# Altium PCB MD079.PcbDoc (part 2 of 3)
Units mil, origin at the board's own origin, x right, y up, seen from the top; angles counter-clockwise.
Board outline 4255 x 2850 mil, 4 copper layers (Top Layer, Ground, Power, Bottom Layer), stack 61.6 mil thick; 171 components, 88 nets, 422 pads, 405 vias.
Unrouted connection lines stored in the file: 3.
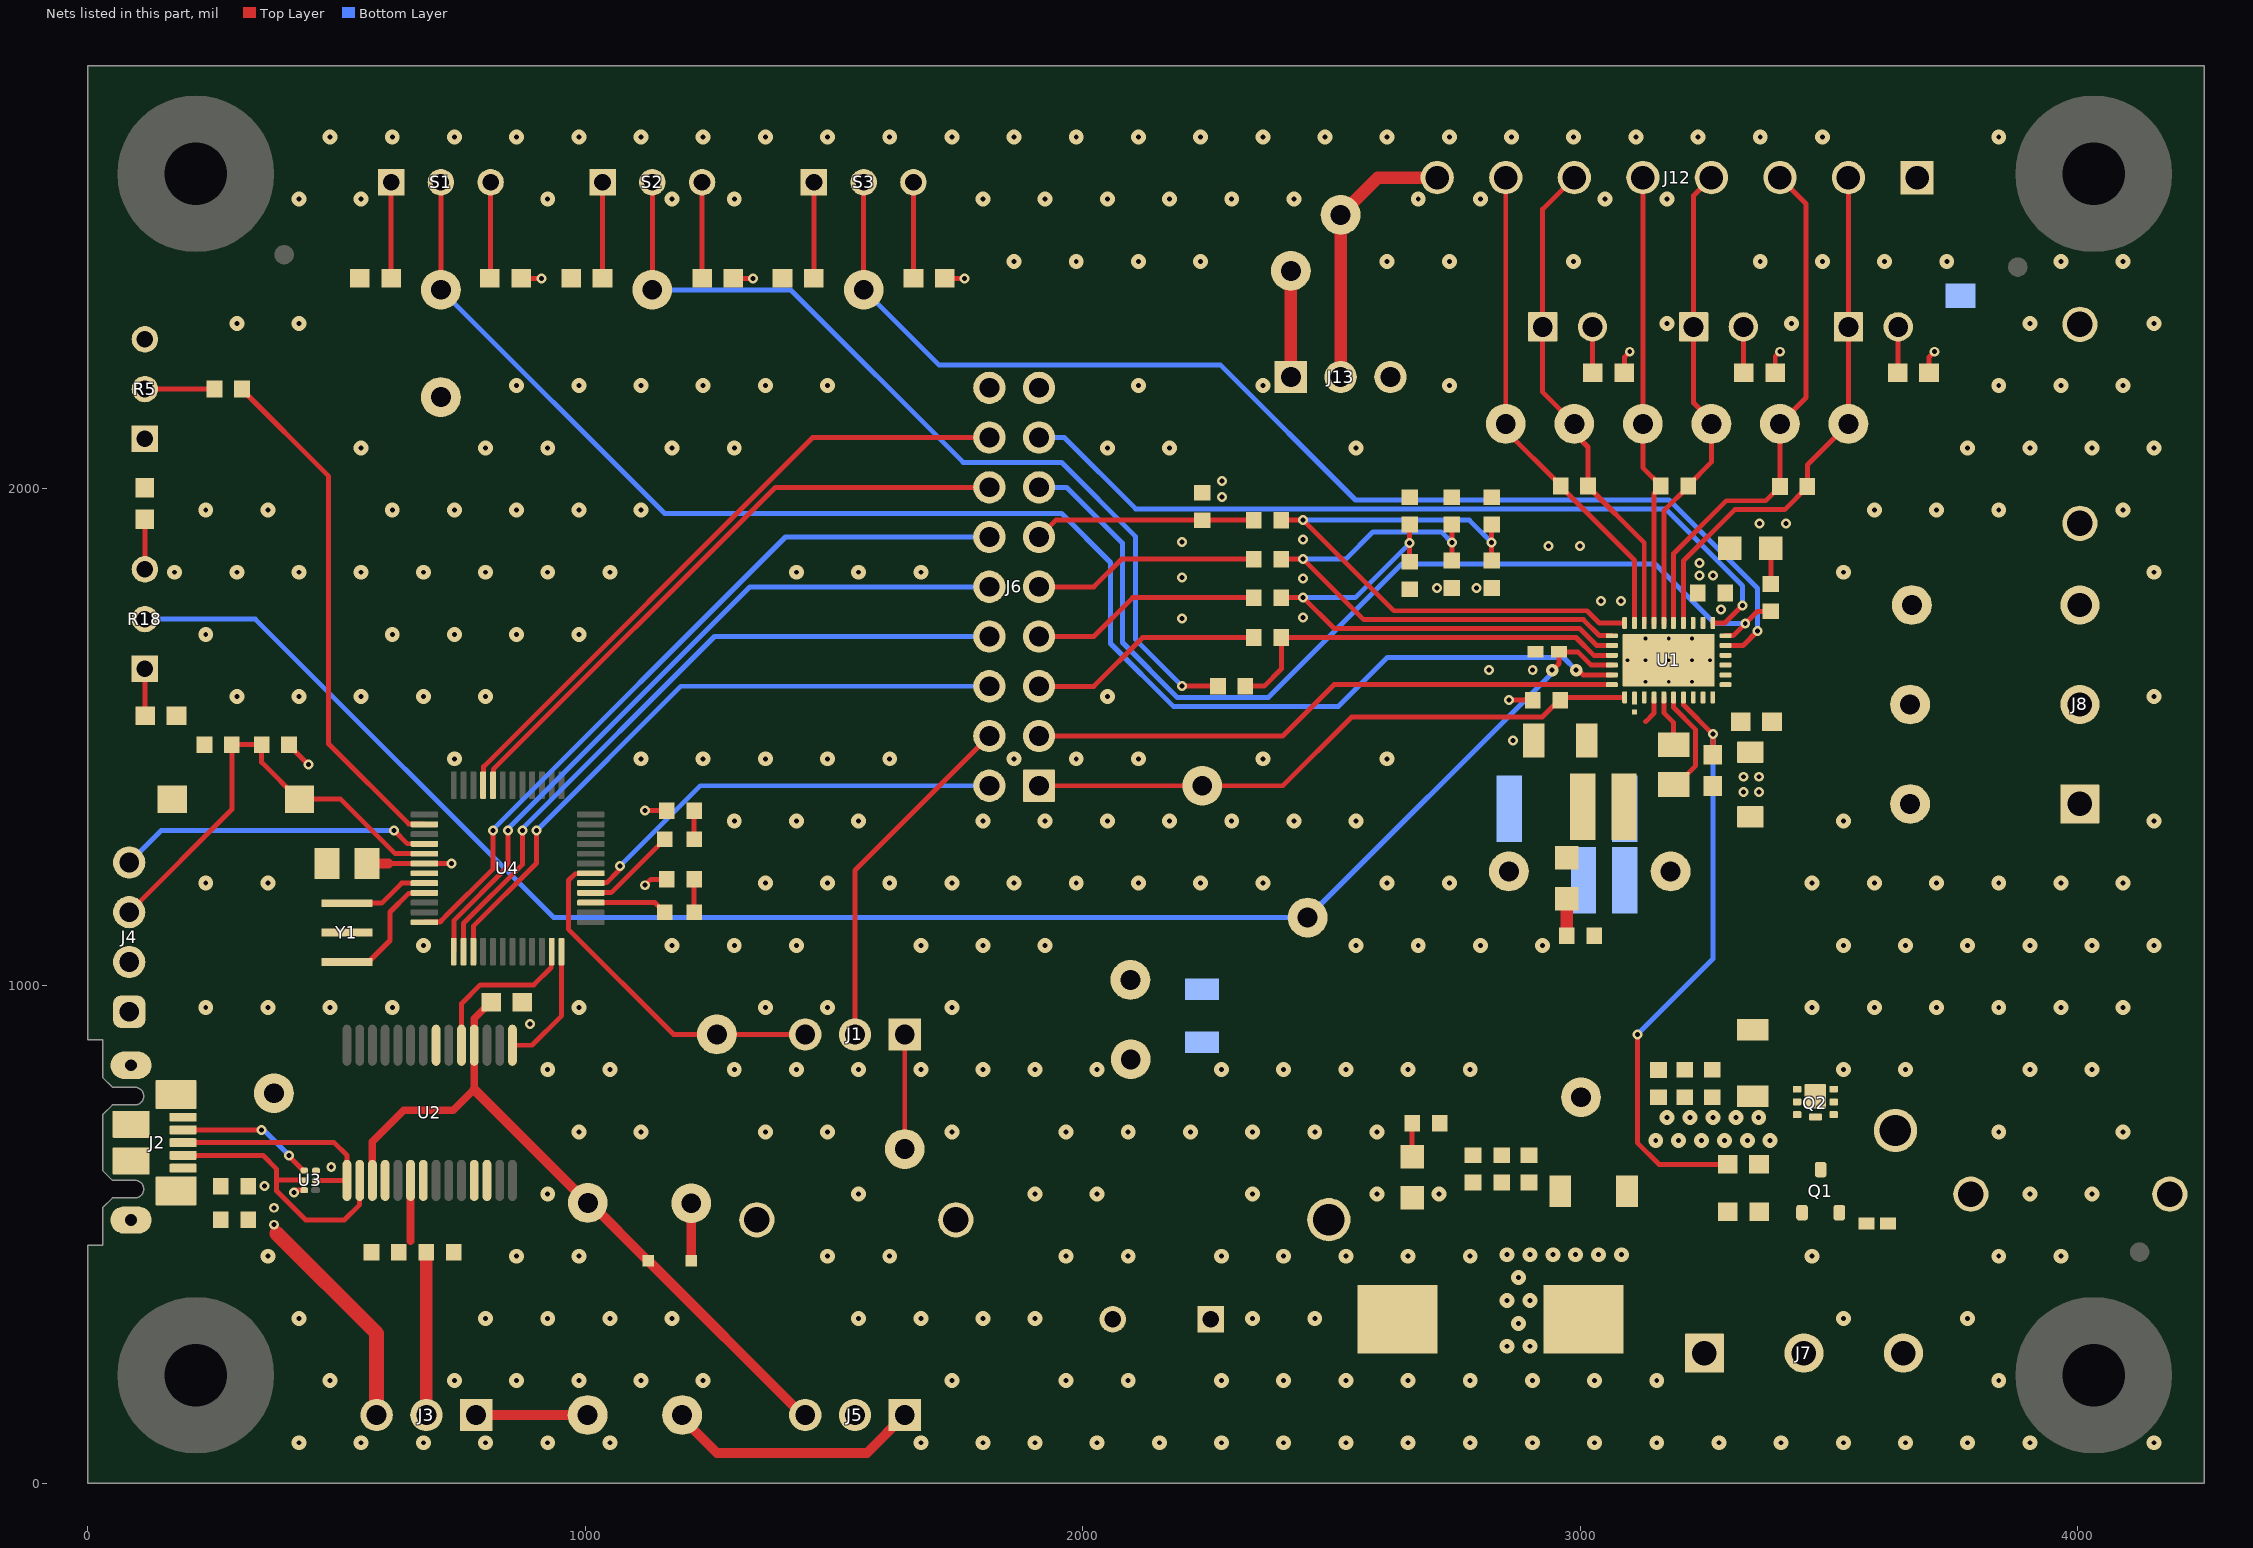
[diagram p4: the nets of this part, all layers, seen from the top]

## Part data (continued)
C17 C20: library part CMP-0007082-4, "CAP, CERM, 0.01 uF, 100 V, +/- 10%, X7R, AEC-Q200 Grade 1, 0603", Cap_Case=0603, Manufacturer=TDK, Supplier Part Number 1=445-5812-1-ND, TempCo=X7R, Tolerance_%=10%, Value1="0.235428 ohm", Value2=100V, ValueDisplayed=0.01uF
C18 C19: library part CMP-0006723-4, "CAP, CERM, 1000 pF, 100 V, +/- 5%, X7R, 0603", Cap_Case=0603, Manufacturer=AVX, Supplier Part Number 1=478-3698-1-ND, TempCo=X7R, Tolerance_%=5%, Value1="0.276 ohm", Value2=100V, ValueDisplayed=1000pF
C23 C24 C25: library part CMP-0083626-1, "CAP, CERM, 0.1 µF, 16 V,+/- 10%, X7R, AEC-Q200 Grade 1, 0603", Cap_Case=0603, Manufacturer=AVX, Supplier Part Number 1=478-9382-1-ND, TempCo=X7R, Tolerance_%=10%, Value2=16V, ValueDisplayed=0.1µF
D1 D3: library part CMP-0002888-2, "LED, Green, SMD", Color=Green, Manufacturer=Lite-On, Value1=W, Value2=2V
D2: library part CMP-0002829-3, "LED, Red, SMD", Color=red, Manufacturer=Lite-On, Value1=W, Value2=2V
D4: library part CMP-0028882-2, "Diode, Schottky, 40 V, 0.75 A, AEC-Q101, SOD-323", Manufacturer="Infineon Technologies", Value1=0.75A, Value2=0.74V
D5: library part CMP-0078131-2, "LED, Red, SMD", Color=Red, Manufacturer=Lite-On, Power_TotalModule=62.5mW, Value1=.0625W, Value2=2V
D6: library part CMP-0002827-3, "LED, Green, SMD", Color=green, Manufacturer=Lite-On, Power_TotalModule=100mW, Value1=0.1W, Value2=2.1V
D7: library part CMP-0076979-3, "Diode, Switching, 100 V, 0.25 A, SOD-523", Manufacturer=Nexperia, Value1=0.25A, Value2=1.25V
FID1 FID2 FID3: library part CMP-0077181-1, "Fiducial mark.  There is nothing to buy or mount.", Manufacturer=N/A
H1 H2 H3 H4: library part CMP-0003617-1, "Machine Screw, Round, #4-40 x 1/4, Nylon, Philips panhead", Manufacturer="B&F Fastener Supply", Supplier Part Number 1=H542-ND
H5 H6 H7 H8: library part CMP-0003610-1, "Standoff, Hex, 0.5\"L #4-40 Nylon", Manufacturer=Keystone, PartNumber=1902C, Supplier Part Number 1=36-1902C-ND
J1 J3 J5 J13: library part CMP-0002334-1, "Header, 100mil, 3x1, Gold, TH", Manufacturer="Sullins Connector Solutions", PartNumber=PBC03SAAN, Supplier Part Number 1=S1011E-03-ND
J2: library part CMP-0055311-1, "Receptacle, USB 2.0, Micro B, 5 Position, R/A, SMT", Color=Black, Current_A=1.8A, Manufacturer=Molex, Supplier Part Number 1=WM11263CT-ND, Voltage_V=30V
J4: library part CMP-0075409-2, "Header, 100mil, 4x1, Gold, TH", Color=Black, Current_A=6.3A, Manufacturer=Samtec, Supplier Part Number 1=SAM1029-04-ND, Voltage_V=550V
J6: library part CMP-0075464-1, "Header, 100mil, 9x2, Gold, TH", Color=Black, Current_A=6.3A, Manufacturer=Samtec, Supplier Part Number 1=SAM1028-09-ND, Voltage_V=550V
J7 J8: library part CMP-0074911-1, "Terminal Block, 5.08 mm, 3x1, Brass, TH", Color=Blue, Current_A=15A, Manufacturer="On-Shore Technology", PartNumber=ED120/3DS, Supplier Part Number 1=ED1610-ND, Voltage_V=300V
J9 J10 J11: library part CMP-0002337-1, "Header, 100mil, 2x1, Tin, TH", Color=Black, Current_A=3A, Manufacturer="Sullins Connector Solutions", Supplier Part Number 1=S1012E-02-ND, Voltage_V=1.8kV
J12: library part CMP-0074957-2, "Terminal Block, 8x1, 3.5mm, TH", Manufacturer="On-Shore Technology", Supplier Part Number 1=ED2641-ND
L1: library part CMP-0064683-2, "Inductor, Shielded, Powdered Iron, 47 uH, 0.39 A, 2.3 ohm, AEC-Q200 Grade 1, SMD", Manufacturer="Wurth Elektronik", Supplier Part Number 1=732-6947-1-ND, Value1="2.3 ohm", Value2=0.39A, ValueDisplayed=47uH
L2: library part CMP-0064681-2, "Inductor, Shielded, Powdered Iron, 22 uH, 0.6 A, 1.04 ohm, AEC-Q200 Grade 1, SMD", Manufacturer="Wurth Elektronik", Supplier Part Number 1=732-6945-1-ND, Value1="1.04 ohm", Value2=0.6A, ValueDisplayed=22uH
L3: library part CMP-0084877-1, "Inductor, Ferrite Bead, Ferrite, 3 A, 120 ohm, AEC-Q200 Grade 1, SMD", Manufacturer=MuRata, Value1="120 ohm", Value2=3A
L4: library part CMP-0056795-1, "Inductor, Shielded, Powdered Iron, 1 uH, 18 A, 0.003 ohm, AEC-Q200 Grade 1, SMD", Manufacturer=Bourns, Supplier Part Number 1=SRP1038A-1R0MCT-ND, Value1="0.003 ohm", Value2=18A, ValueDisplayed=1uH
LBL1: library part CMP-0003625-1, Manufacturer=Brady, Supplier Part Number 1=97C5133
Logo1: library part CMP-0074844-1
Logo2: library part CMP-0074838-1, "Texas Instrument Corporate Signature"
Logo3: library part CMP-0074847-1, "FCC_disclaimer"
Logo4: library part CMP-0074769-3, Manufacturer="Texas Instruments"
LOGO5 LOGO6: library part CMP-0074837-2, "IEC 61010-1 Hot Surface Warning", Manufacturer="Texas Instruments"
NT1 NT2: library part CMP-0078142-6, "Single point connection between nets.", Manufacturer=N/A
Q1: library part CMP-0000467-2, "Transistor, NPN, 80 V, 1.5 A, AEC-Q101, SOT-23", Manufacturer="Diodes Inc.", Supplier Part Number 1=FMMT620CT-ND, Value1="1.5 A", Value2=900
Q2: library part CMP-0088880-1, "N-Channel 40V 8A (Ta) 15W (Tc) Surface Mount DFN2020MD-6", Digikey Part Number=1727-7413-1-ND, Drain To Source Breakdown Voltage=40V, Input Capacitace At Vds="637pF @ 20V", Manufacturer=Nexperia, Mouser Part Number=771-BUK9D23-40EX, Operating Temperature Range="-55°C to +175°C", Power_W=2.3W, Pulse Drain Current=76A, Typ Forward Diode Voltage=0.8V
R1 R2 R3 R6 R7 R8 R32 R33 R34 R35 R36: library part CMP-0022746-5, "RES, 10.0 k, 1%, 0.1 W, 0603", Manufacturer=Yageo, Power_W=100mW, Supplier Part Number 1=311-10.0KHRCT-ND, TempCo="100 ppm/C", Tolerance_%=1%, Value2=0.1W, Value_Code=10k0, ValueDisplayed=10.0k
R4 R13 R14 R15 R16 R17 R21 R26 R27: library part CMP-0025874-4, "RES, 0, 5%, 0.1 W, AEC-Q200 Grade 0, 0603", Manufacturer=Panasonic, Power_W=100mW, Supplier Part Number 1=P0.0GCT-ND, TempCo="600 ppm/C", Tolerance_%=5%, Value2=0.1W, Value_Code=0000, ValueDisplayed=0
R5: library part CMP-0001776-2, "Trimmer Potentiometer, 25kohm, 0.5W, TH", Manufacturer=Bourns, Supplier Part Number 1=3352T-253LF-ND
R9 R12: library part CMP-0025830-4, "RES, 5.1 k, 5%, 0.1 W, AEC-Q200 Grade 0, 0603", Manufacturer=Vishay-Dale, Power_W=100mW, Supplier Part Number 1=541-5.1KGCT-ND, TempCo="200 ppm/C", Tolerance_%=5%, Value2=0.1W, Value_Code=5k10, ValueDisplayed=5.1k
R10: library part CMP-0015919-3, "RES, 22, 5%, 1.5 W, AEC-Q200 Grade 0, 2512", Manufacturer=Vishay-Dale, Power_W=1.5W, TempCo="200 ppm/C", Tolerance_%=5%, Value_Code=22R0, ValueDisplayed=22
R11: library part CMP-0023166-5, "RES, 51.1 k, 1%, 0.1 W, 0603", Manufacturer=Yageo, Power_W=100mW, Supplier Part Number 1=311-51.1KHRCT-ND, TempCo="100 ppm/C", Tolerance_%=1%, Value2=0.1W, Value_Code=51k1, ValueDisplayed=51.1k
R18: library part CMP-0093882-3, "10 kOhms 0.5W, 1/2W Through Hole Thumbwheel Potentiometer Top Adjustment", Digikey Part Number=3352T-103LF-ND, Manufacturer=Bourns, Mouser Part Number=652-3352T-1-103LF, Operating Temperature Range="-55°C to +125°C", Power=500mW, Power_W=0.5W, TempCo=100ppm/°C, Tolerance_%=20%, Voltage=250V
R19: library part CMP-0023102-5, "RES, 41.2 k, 1%, 0.1 W, 0603", Manufacturer=Yageo, Power_W=100mW, Supplier Part Number 1=311-41.2KHRCT-ND, TempCo="100 ppm/C", Tolerance_%=1%, Value2=0.1W, Value_Code=41k2, ValueDisplayed=41.2k
R20 R28: library part CMP-0023363-3, "RES, 100 k, 0.1%, 0.1 W, AEC-Q200 Grade 0, 0603", Manufacturer=Panasonic, Power_W=100mW, Supplier Part Number 1=P100KDBCT-ND, TempCo="25 ppm/C", Tolerance_%=0.1%, Value2=0.1W, Value_Code=100k
R22: library part CMP-0022692-3, "RES, 22.0 k, 1%, 0.1 W, AEC-Q200 Grade 0, 0603", Manufacturer=Panasonic, Power_W=100mW, Supplier Part Number 1=P22.0KHCT-ND, TempCo="100 ppm/C", Tolerance_%=1%, Value2=0.1W, Value_Code=22k0, ValueDisplayed=22.0k
R23: library part CMP-0023033-5, "RES, 330, 1%, 0.1 W, 0603", Manufacturer=Yageo, Power_W=100mW, Supplier Part Number 1=311-330HRCT-ND, TempCo="100 ppm/C", Tolerance_%=1%, Value2=0.1W, Value_Code=330R, ValueDisplayed=330
R24: library part CMP-0025899-5, "RES, 1.0 k, 5%, 0.1 W, 0603", Manufacturer=Yageo, Power_W=100mW, Supplier Part Number 1=311-1.0KGRCT-ND, TempCo="100 ppm/C", Tolerance_%=5%, Value2=0.1W, Value_Code=1k00, ValueDisplayed=1.0k
R25: library part CMP-0024300-2, "RES, 4.70 k, 0.1%, 0.1 W, 0603", Manufacturer="Yageo America", Power_W=100mW, TempCo="25 ppm/C", Tolerance_%=0.1%, Value2=0.1W, Value_Code=4k70, ValueDisplayed=4.70k
R29: library part CMP-0025925-5, "RES, 47 k, 5%, 0.1 W, 0603", Manufacturer=Yageo, Power_W=100mW, Supplier Part Number 1=311-47KGRCT-ND, TempCo="100 ppm/C", Tolerance_%=5%, Value2=0.1W, Value_Code=47k0, ValueDisplayed=47k
R30 R31: library part CMP-0025924-5, "RES, 470, 5%, 0.1 W, 0603", Manufacturer=Yageo, Power_W=100mW, Supplier Part Number 1=311-470GRCT-ND, TempCo="100 ppm/C", Tolerance_%=5%, Value2=0.1W, Value_Code=470R, ValueDisplayed=470
R37: library part CMP-0018760-2, "RES, 0, 5%, 0.25 W, AEC-Q200 Grade 0, 1206", Manufacturer=Vishay-Dale, Power_W=250mW, Supplier Part Number 1=541-2239-1-ND, TempCo=ppm/C, Tolerance_%=5%, Value2=0.25W, Value_Code=0000, ValueDisplayed=0
S1 S2 S3: library part CMP-0002155-2, "SWITCH TOGGLE SPDT 0.4VA 28V", CurrentRating_mA=100A, Manufacturer="NKK Switches", PartNumber=B12AP, Supplier Part Number 1=360-1012-ND
S4: library part CMP-0002196-2, "Switch, Tactile, SPST, 12 V, SMD", CurrentRating_mA=50A, Manufacturer="Wurth Elektronik", PartNumber=434121025816, Supplier Part Number 1=31T8978
SH-J1 SH-J2 SH-J3 SH-J4 SH-J5 SH-J6 SH-J7 SH-J8 SH-J9 SH-J10 SH-J11 SH-J12 SH-J13 SH-J14 SH-J15 SH-J16: library part CMP-0003623-3, "Shunt, 100mil, Gold plated, Black", Alternate Manufacturer=3M, Alternate PartNumber=969102-0000-DA, Manufacturer=Samtec, Supplier Part Number 1=SAM8858-ND
TP1 TP2 TP3 TP4 TP5 TP11 TP12 TP21 TP22 TP28 TP29 TP30 TP31: library part CMP-0055139-2, "Test Point, Miniature, White, TH", Color=White, Manufacturer="Keystone Electronics", PartNumber=5002, Supplier Part Number 1=36-5002-ND
TP6 TP7 TP8 TP9 TP10 TP13 TP14 TP23 TP27 TP32 TP33 TP34: library part CMP-0055137-2, "Test Point, Miniature, Red, TH", Color=Red, Manufacturer="Keystone Electronics", PartNumber=5000, Supplier Part Number 1=36-5000-ND
TP15 TP16: library part CMP-0055142-2, "Test Point, Compact, Red, TH", Color=Red, Manufacturer="Keystone Electronics", PartNumber=5005, Supplier Part Number 1=36-5005-ND
TP17 TP24 TP25 TP26: library part CMP-0055138-2, "Test Point, Miniature, Black, TH", Color=Black, Manufacturer="Keystone Electronics", PartNumber=5001, Supplier Part Number 1=36-5001-ND
TP18 TP19 TP20: library part CMP-0075110-1, "1mm Uninsulated Shorting Plug, 10.16mm spacing, TH", Manufacturer=Harwin, PartNumber=D3082-05, Supplier Part Number 1=952-1873-ND
U1: library part CMP-0098493-1, Manufacturer="Texas Instruments", Operating Temperature Range=to
U2: library part CMP-0004774-1, "USB to Serial UART, SSOP28", Manufacturer=FTDI, Supplier Part Number 1=768-1007-1-ND
U3: library part CMP-0043115-3, "4-Channel ESD Protection Array for High-Speed Data Interfaces, DRY0006A (USON-6)", Breakdown Voltage(Min)(V)=6, IO Capacitance(Typ)(pF)=1.6, IO Leakage Current(nA)=1, Manufacturer="Texas Instruments", Operating Temperature Range="-40 to 85 C", Rating=Catalog
U4: library part CMP-0089204-1, "CPU16 MSP430™ FRAM Microcontroller IC 16-Bit 24MHz 32KB (32K x 8) FRAM 48-LQFP (7x7)", Digikey Part Number=296-50261-1-ND, Frequency_Fixed=24MHz, Manufacturer="Texas Instruments", Max Supply Voltage=3.6V, Min Supply Voltage=1.8V, Mouser Part Number=595-MSP430FR2355TPTR, Operating Temperature Range="-40°C to +105°C"
Y1: library part CMP-0084387-1, "Resonator, 4 MHz, 39 pF, AEC-Q200 Grade 1, SMD", Frequency_Fixed=4MHz, Load Capacitance="39 pF", Manufacturer=MuRata
ZZ1: library part CMP-0003616-3
ZZ2: library part CMP-0077236-1
ZZ3: library part CMP-0077237-1
ZZ4: library part CMP-0077238-1

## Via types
v1: diameter 30, hole 10, Top Layer to Bottom Layer, tented both sides, 328 vias
v2: diameter 20, hole 10, Top Layer to Bottom Layer, tented both sides, 32 vias
v3: diameter 20, hole 10, Top Layer to Bottom Layer, 32 vias
v4: diameter 19.68, hole 7.87, Top Layer to Bottom Layer, tented both sides, 11 vias
v5: diameter 25, hole 10, Top Layer to Bottom Layer, 2 vias

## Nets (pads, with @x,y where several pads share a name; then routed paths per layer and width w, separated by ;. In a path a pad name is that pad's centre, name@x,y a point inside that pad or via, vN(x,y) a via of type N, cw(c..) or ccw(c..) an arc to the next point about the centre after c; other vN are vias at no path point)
3V3_MCU: C13.1 D4.1 J4.2 J5.2 R29.2 R30.2 R31.2 TP34.1 U4.6 | length 435.1
  Top Layer w10: R29.2@404.76,1485.08 404.76,1484.09 v3(443.86,1445) ; 605,1246.18 677.88,1246.18 731.55,1246.18 v3(731.68,1246.32) ; v3(1120.21,1202.5) 1131.97,1214.26 R31.2@1163.95,1214.26 ; v3(1120.21,1352.5) R30.2@1163.95,1352.5
  Top Layer w20: C13.1@561.16,1246.18 605,1246.18 ; D4.1@1213.31,447.36 TP34.1@1213.31,563.23
3V3COM: C9.1 D4.2 J5.3 TP32.1 U2.4 U2.17 | length 1452.3
  Top Layer w10: C9.1@810.02,967.5 C9.1@811,967.5 ; J5.3@1437.11,137.5 J5.3@1442.5,137.5
  Top Layer w15: U2.17@572.34,609.17 572.34,686.63 635.71,750 734.91,750 777.07,792.16 U2.4@777.07,880.83 777.07,934.55 C9.1@810.02,967.5
  Top Layer w20: 777.07,792.16 TP32.1@1005.39,563.83 1010.22,563.83 D4.2@1126.69,447.36 ; D4.2@1126.97,447.64 J5.3@1437.11,137.5
3V3EXT: J5.1 TP14.1 | length 514.2
  Top Layer w10: TP14.1@1195,131.31 TP14.1@1195,137.5
  Top Layer w20: TP14.1@1195,131.31 1264.93,61.38 1566.38,61.38 J5.1@1642.5,137.5
5V_EXT: J3.1 TP13.1 | length 224.1
  Top Layer w20: J3.1@780.89,137.5 TP13.1@1005.02,137.5
5V_USB: C8.1 J3.3 L3.1 TP33.1 U3.6 | length 470.5
  Top Layer w10: v2(415,585) 419.49,589.49 U3.6@435.35,589.49
  Top Layer w30: 380,502.56 580.89,301.68 J3.3@580.89,137.5
  other v2: 374.4,520 374.4,554.09 355.28,597.5
5VCC: C10.2 C11.1 J3.2 U2.20 | length 450.4
  Top Layer w10: C10.2@625.49,464.83 C10.2@625.49,465.81
  Top Layer w16: 649.11,487.02 U2.20@649.11,609.17
  Top Layer w25: J3.2@680.89,137.5 C11.1@680.82,464.83
AGND: C2.1 C6.2 C7.2 C8.2 C9.2 C10.1 C11.2 C12.2 C13.2 J2.5 J2.6 J2.7 J2.8 J2.9 J2.10 J2.11 J4.1 J6.17 J6.18 J12.1 NT2.1 R5.3 R6.1 R7.1 R8.1 R19.1 R23.1 R26.1 R27.1 R28.1 R37.1 S4.2 TP18.1 TP18.2 TP24.1 TP25.1 U1.3 U1.18 U1.33 U2.7 U2.18 U2.21 U2.25 U2.26 U3.3 U4.7 Y1.2
  other v1: 424.81,81.7 549.81,81.7 674.81,81.7 799.81,81.7 924.81,81.7 1049.81,81.7 1674.81,81.7 1799.81,81.7 487.31,206.7 737.31,206.7 862.31,206.7 987.31,206.7 1112.31,206.7 1237.31,206.7 1737.31,206.7 424.81,331.7 799.81,331.7 924.81,331.7 1049.81,331.7 1174.81,331.7 1549.81,331.7 1674.81,331.7 1799.81,331.7 362.31,456.7 862.31,456.7 987.31,456.7 1487.31,456.7 1612.31,456.7 924.81,581.7 1549.81,581.7 987.31,706.7 1112.31,706.7 1362.31,706.7 1487.31,706.7 1737.31,706.7 924.81,831.7 1049.81,831.7 1299.81,831.7 1424.81,831.7 1549.81,831.7 1674.81,831.7 1799.81,831.7 237.31,956.7 362.31,956.7 487.31,956.7 612.31,956.7 987.31,956.7 1362.31,956.7 1487.31,956.7 1737.31,956.7 674.81,1081.7 1174.81,1081.7 1299.81,1081.7 1424.81,1081.7 1674.81,1081.7 1799.81,1081.7 1924.81,1081.7 2549.81,1081.7 2674.81,1081.7 2799.81,1081.7 2924.81,1081.7 237.31,1206.7 362.31,1206.7 1362.31,1206.7 1487.31,1206.7 1612.31,1206.7 1737.31,1206.7 1862.31,1206.7 1987.31,1206.7 2112.31,1206.7 2237.31,1206.7 2362.31,1206.7 2612.31,1206.7 2737.31,1206.7 1299.81,1331.7 1424.81,1331.7 1549.81,1331.7 1799.81,1331.7 1924.81,1331.7 2049.81,1331.7 2174.81,1331.7 2299.81,1331.7 2424.81,1331.7 2549.81,1331.7 737.31,1456.7 1112.31,1456.7 1237.31,1456.7 1362.31,1456.7 1487.31,1456.7 1612.31,1456.7 1862.31,1456.7 1987.31,1456.7 2112.31,1456.7 2362.31,1456.7 2612.31,1456.7 299.81,1581.7 424.81,1581.7 549.81,1581.7 674.81,1581.7 799.81,1581.7 2049.81,1581.7 237.31,1706.7 612.31,1706.7 737.31,1706.7 862.31,1706.7 987.31,1706.7 174.81,1831.7 299.81,1831.7 424.81,1831.7 549.81,1831.7 674.81,1831.7 799.81,1831.7 924.81,1831.7 1049.81,1831.7 1424.81,1831.7 1549.81,1831.7 1674.81,1831.7 237.31,1956.7 362.31,1956.7 612.31,1956.7 737.31,1956.7 862.31,1956.7 987.31,1956.7 1112.31,1956.7 549.81,2081.7 799.81,2081.7 924.81,2081.7 1174.81,2081.7 1299.81,2081.7 2049.81,2081.7 2174.81,2081.7 2549.81,2081.7 862.31,2206.7 987.31,2206.7 1112.31,2206.7 1237.31,2206.7 1362.31,2206.7 1487.31,2206.7 2112.31,2206.7 2362.31,2206.7 2737.31,2206.7 299.81,2331.7 424.81,2331.7 3174.81,2331.7 3424.81,2331.7 1862.31,2456.7 1987.31,2456.7 2112.31,2456.7 2237.31,2456.7 2612.31,2456.7 2737.31,2456.7 2987.31,2456.7 3362.31,2456.7 3487.31,2456.7 3612.31,2456.7 3737.31,2456.7 424.81,2581.7 549.81,2581.7 924.81,2581.7 1174.81,2581.7 1299.81,2581.7 1799.81,2581.7 1924.81,2581.7 2049.81,2581.7 2174.81,2581.7 2299.81,2581.7 2424.81,2581.7 2674.81,2581.7 2799.81,2581.7 3049.81,2581.7 3174.81,2581.7 487.31,2706.7 612.31,2706.7 737.31,2706.7 862.31,2706.7 987.31,2706.7 1112.31,2706.7 1237.31,2706.7 1362.31,2706.7 1487.31,2706.7 1612.31,2706.7 1737.31,2706.7 1862.31,2706.7 1987.31,2706.7 2112.31,2706.7 2237.31,2706.7 2362.31,2706.7 2487.31,2706.7 2612.31,2706.7 2737.31,2706.7 2862.31,2706.7 2987.31,2706.7 3112.31,2706.7 3237.31,2706.7 3362.31,2706.7 3487.31,2706.7
  other v2: 489.63,636.25 889.18,923.3 2865.23,1493.52 2816.65,1635 2904.94,1635 2200.08,1739.02 2443.52,1740.3 3283.19,1756.59 3042.41,1773.43 3082.48,1773.43 2712.93,1800.18 2791.61,1800.18 2443.52,1819.15 2200.08,1821.4 2937.06,1884.22 3000.37,1884.22 2200.08,1892.72 2443.52,1897.32 3360.37,1930 3414.07,1930
  other v4: 3131.87,1611.54 3178.33,1611.54 3224.78,1611.54 3095.65,1654.84 3131.87,1654.84 3178.33,1654.84 3224.78,1654.84 3261,1654.84 3131.87,1698.15 3178.33,1698.15 3224.78,1698.15
AVDD: C2.2 D2.1 R1.2 R2.2 R3.2 R5.1 R9.2 R11.2 R12.2 R20.2 R21.2 R22.2 R34.1 R35.1 R36.1 U1.19 | length 308
  Top Layer w10: R1.2@871.5,2422.5 v3(912.48,2422.5) ; R2.2@1298.02,2422.52 v3(1337.45,2422.52) ; R3.2@1723.16,2422.64 v3(1762.36,2422.64) ; v3(2857.07,1574.6) R9.2@2904.94,1574.6 ; R36.1@3089,2232.5 3089,2264 v3(3100,2275) ; R35.1@3392.5,2232.5 3392.5,2265.59 v3(3401.91,2275) ; R34.1@3701.5,2232.5 3701.5,2264 v3(3712.5,2275)
  other v2: 3240,1825 3266.91,1825 3240,1850 2280,1982.76 2280,2015
BRAKE: S1.2 TP3.1 U1.31 | length 3067.7
  Top Layer w10: TP3.1@710,2399.51 S1.2@710,2615.63 ; v5(2992.2,1634.94) 2996.26,1634.94 3005.89,1625.31 U1.31@3064.15,1625.31
  Bottom Layer w10: TP3.1@710,2399.51 1159.51,1950 1957.5,1950 2056.28,1851.22 2056.28,1688.32 2182.51,1562.09 2514.47,1562.09 2612.63,1660.26 2966.89,1660.26 v5(2992.2,1634.94)
CLK: J6.7 R13.1 | length 464.3
  Top Layer w10: J6.7@1912.5,1702.5 2022.5,1702.5 2100.64,1780.64 R13.1@2344.39,1780.64
CPH: C5.1 U1.6 | length 215.6
  Top Layer w10: C5.1@3188.17,1405 3194.67,1405 3232.54,1442.87 3232.54,1515.33 3188.25,1559.62 3188.25,1579.96 U1.6@3188.17,1580.04
CPL: C5.2 U1.5 | length 103.2
  Top Layer w10: U1.5@3168.48,1580.04 3168.48,1548.99 3188.17,1529.31 C5.2@3188.17,1485
DIR: R17.1 S2.2 TP4.1 | length 1804.5
  Top Layer w10: TP4.1@1135,2399.51 S2.2@1135,2615.63 ; v3(2200.05,1602.84) R17.1@2272.07,1602.81
  Bottom Layer w10: TP4.1@1135,2399.51 1412.99,2399.51 1760,2052.5 1957.5,2052.5 2106.64,1903.36 2106.64,1696.25 v3(2200.05,1602.84)
DM: J2.2 U2.16 U3.5 | length 551.5
  Top Layer w10: J2.2@191.81,659.41 352.34,659.41 380,631.75 380,609.7 ; U3.5@435.35,609.17 434.83,609.7 380,609.7 ; U2.16@546.75,609.17 546.75,560.33 516.25,529.83 437.83,529.83 380,587.65 380,609.7
DP: J2.3 U2.15 U3.2 | length 452.4
  Top Layer w10: J2.3@191.81,685 495.57,685 521.16,659.41 U2.15@521.16,609.17 U3.2@458.97,609.17
DRVOFF: S3.2 TP5.1 U1.15 | length 2424.1
  Top Layer w10: TP5.1@1560,2399.51 S3.2@1560,2615.63 ; U1.15@3292.58,1684.45 U1.15@3292.5,1684.37 3327.87,1684.37 v3(3356.94,1713.44)
  Bottom Layer w10: TP5.1@1560,2399.51 1711.65,2247.85 2277.73,2247.85 2548.51,1977.08 3179.18,1977.08 3356.94,1799.33 v3(3356.94,1713.44)
FB_BUCK: NT1.1 U1.2
FGOUT: J6.1 R9.1 TP11.1 U1.1 | length 1250.8
  Top Layer w10: J6.1@1912.5,1402.5 2217.5,1402.5 2402.68,1402.5 2541.02,1540.84 2924.37,1540.84 2963.56,1580.04 U1.1@3089.74,1580.04
HALL_EXT: J13.1 TP23.1 | length 213.4
  Top Layer w25: J13.1@2418.77,2224.15 TP23.1@2418.77,2437.5
HALL_PWR: J12.8 J13.2 TP27.1 | length 551.1
  Top Layer w25: J13.2@2518.77,2224.15 TP27.1@2518.77,2550 2593.77,2625 J12.8@2712.93,2625
HNA: C25.1 J12.3 TP30.1 U1.21 | length 1074.2
  Top Layer w10: U1.21@3188.17,1729.65 3188.17,1869.27 3294.31,1975.41 3373.3,1975.41 3390.18,1992.28 3391.16,1992.28 3401.91,2003.03 C25.1@3401.91,2004.02 TP30.1@3401.91,2130 3454.41,2182.5 3454.41,2572.5 J12.3@3401.91,2625
HNB: C24.1 J12.5 TP28.1 U1.23 | length 915.8
  Top Layer w10: J12.5@3126.32,2625 TP28.1@3126.32,2130 3126.32,2041.85 3162.18,2005.98 C24.1@3162.18,2005 3162.18,2004.02 3148.8,1990.63 U1.23@3148.8,1729.65
HNC: C23.1 J12.7 TP21.1 U1.25 | length 1002.5
  Top Layer w10: J12.7@2850.73,2625 TP21.1@2850.73,2130 2850.73,2116.22 2960.96,2005.98 C23.1@2960.96,2005 2960.96,2004.02 3109.43,1855.55 U1.25@3109.43,1729.65
HPA: C25.2 J9.1 J12.2 TP31.1 U1.20 | length 1091.7
  Top Layer w10: U1.20@3207.85,1729.65 3207.85,1854.35 3311.04,1957.54 3411.53,1957.54 3457.03,2003.03 C25.2@3457.03,2004.02 3457.03,2047.38 TP31.1@3539.65,2130 J9.1@3539.65,2325 3539.7,2325.06 J12.2@3539.7,2625
HPB: C24.2 J10.1 J12.4 TP29.1 U1.22 | length 964.6
  Top Layer w10: U1.22@3168.48,1729.65 3168.48,1955.2 3217.3,2004.02 C24.2@3217.3,2005 3217.3,2005.98 3264.11,2052.8 TP29.1@3264.11,2130 3264.11,2136.21 3228.33,2171.99 J10.1@3228.33,2325 3228.33,2589.21 J12.4@3264.11,2625
HPC: C23.2 J11.1 J12.6 TP22.1 U1.24 | length 1006.2
  Top Layer w10: J12.6@2988.52,2625 2925,2561.48 J11.1@2925,2325 2925,2193.52 TP22.1@2988.52,2130 2988.52,2111.06 3016.08,2083.5 C23.2@3016.08,2005 3016.08,2004.02 3129.11,1890.98 U1.24@3129.11,1729.65
ID: J2.4 U3.4 | length 278.5
  Top Layer w10: J2.4@191.81,710.59 v3(349.65,710.59) ; v3(404.76,659.41) 404.76,657.48 433.38,628.86 U3.4@435.35,628.86
  Bottom Layer w10: v3(349.65,710.59) 353.58,710.59 v3(404.76,659.41)
ILIM: C7.1 R18.2 TP12.1 U1.30 | length 3446.6
  Top Layer w10: v5@2944.82,1634.94 2957.64,1647.76 C7.1@2957.64,1671.75 2995.55,1671.75 3022.3,1645 U1.30@3064.15,1645
  Bottom Layer w10: R18.2@115,1737.5 115.04,1737.46 336.86,1737.46 936.82,1137.5 TP12.1@2452.32,1137.5 2941.02,1626.2 2941.02,1632.01 v5(2943.89,1634.88)
MSP_CLK_P4.5: J6.8 U4.14 | length 1393.8
  Top Layer w10: U4.14@755.64,1070 755.64,1125.76 873.75,1243.87 v3(873.75,1312.5)
  Bottom Layer w10: v3(873.75,1312.5) 875.66,1314.41 875.66,1318.01 1260.15,1702.5 J6.8@1812.5,1702.5
MSP_FGOUT_P2.1: J6.2 U4.29 | length 886.4
  Top Layer w10: U4.29@1010.56,1206.81 U4.29@1010.9,1207.16 ; U4.29@1011.54,1206.81 1012.45,1207.72 1043.29,1207.72 1067.81,1232.24 1067.81,1238.85 v3(1069.72,1240.76)
  Bottom Layer w10: v3(1069.72,1240.76) 1231.46,1402.5 J6.2@1812.5,1402.5
MSP_LED0_P2.2: D5.2 U4.28 | length 194.2
  Top Layer w10: U4.28@1010.56,1187.13 1010.9,1187.47 1052.32,1187.47 D5.2@1160,1295.15
MSP_LED1_P2.3: D6.2 U4.27 | length 157.5
  Top Layer w10: U4.27@1010.56,1167.44 1140.6,1167.44 D6.2@1160,1148.04
MSP_nFAULT_P3.3: J6.14 U4.44 | length 1264.4
  Top Layer w10: U4.44@814.69,1402.68 U4.44@815.04,1403.02 ; U4.44@814.69,1403.66 815.6,1404.57 815.6,1435.41 1382.68,2002.5 J6.14@1812.5,2002.5
MSP_nSLEEP_P3.2: J6.16 U4.45 | length 1329.3
  Top Layer w10: U4.45@795.01,1402.68 795.91,1403.58 795.91,1441 1457.41,2102.5 J6.16@1812.5,2102.5
MSP_POT_P1.1: R4.1 U4.2 | length 1045.1
  Top Layer w10: R4.1@310.06,2200 310.06,2199.02 484.41,2024.66 484.41,1486.56 645.15,1325.83 675.99,1325.83 U4.2@676.9,1324.92
MSP_PWM_P2.0: J1.3 TP1.1 U4.30 | length 713.5
  Top Layer w10: U4.30@1010.21,1226.15 U4.30@1010.56,1226.5 ; U4.30@1011.54,1226.5 1010.64,1225.59 979.79,1225.59 966.27,1212.07 966.27,1114.29 1178.06,902.5 TP1.1@1264.93,902.5 J1.3@1442.5,902.5
MSP_RX_P4.3: U2.5 U4.23 | length 326.9
  Top Layer w10: U2.5@751.48,880.83 751.48,964.56 789.27,1002.35 896.98,1002.35 931.9,1037.27 931.9,1068.11 U4.23@932.8,1069.02 ; U4.23@932.45,1069.65 U4.23@932.8,1070
MSP_SBWTCK: J4.4 U4.4 | length 632.2
  Top Layer w10: v3(616.08,1312.5) 642.69,1285.9 677.53,1285.9 U4.4@677.88,1285.55
  Bottom Layer w10: J4.4@83.45,1248.24 147.71,1312.5 v3(616.08,1312.5)
MSP_SBWTDIO/nRST: C12.1 J4.3 R29.1 S4.1 U4.5 | length 922.4
  Top Layer w10: J4.3@83.45,1148.24 289.91,1354.71 C12.1@289.91,1485.08 R29.1@349.65,1485.08 349.65,1449.58 423.78,1375.44 S4.1@425.75,1375.44 508.66,1375.44 618.24,1265.87 677.88,1265.87 U4.5@677.53,1266.21
MSP_SIMO_P4.6: J6.10 U4.13 | length 1460.2
  Top Layer w10: U4.13@735.95,1070 735.95,1131.35 845,1240.4 v3(845,1312.5)
  Bottom Layer w10: v3(845,1312.5) 846.91,1314.41 846.91,1318.02 1331.4,1802.5 J6.10@1812.5,1802.5
MSP_SOMI_P4.7: J6.12 U4.12 | length 1503
  Top Layer w10: U4.12@676.9,1128.07 677.24,1128.42 708.09,1128.42 718.08,1138.41 718.08,1138.76 815.04,1235.72 v3(815.04,1312.5)
  Bottom Layer w10: v3(815.04,1312.5) 815.04,1314.89 1402.65,1902.5 J6.12@1812.5,1902.5
MSP_STE_P4.4: J6.6 U4.15 | length 1325.3
  Top Layer w10: U4.15@775.32,1070 775.32,1120.17 902.5,1247.35 v3(902.5,1312.5)
  Bottom Layer w10: v3(902.5,1312.5) 1192.5,1602.5 J6.6@1812.5,1602.5
MSP_TX_P4.2: U2.1 U4.24 | length 253.2
  Top Layer w10: U2.1@853.84,880.83 893.21,880.83 952.68,940.3 U4.24@952.49,1070
MSP_XIN_P2.7: U4.8 Y1.1 | length 173.5
  Top Layer w10: Y1.1@521.16,1166.35 590.82,1166.35 631.28,1206.81 U4.8@677.88,1206.81
MSP_XOUT_P2.6: U4.9 Y1.3 | length 246.8
  Top Layer w10: Y1.3@521.16,1048.24 564.47,1048.24 607.68,1091.45 607.68,1148.76 645.15,1186.22 650.74,1186.22 675.89,1186.22 U4.9@676.85,1187.17
NetC15_1: C15.1 C16.1 C17.1 C18.1 L4.1 Q2.1 Q2.2 Q2.5 Q2.6 Q2.7
  other v1: 2853.27,275.7 2899.27,275.7 2876.27,321.7 2853.27,367.7 2899.27,367.7 2876.27,413.7 2853.27,459.7 2899.27,459.7 2945.27,459.7 2991.27,459.7 3037.27,459.7 3083.27,459.7 3152.27,689.7 3198.27,689.7 3244.27,689.7 3290.27,689.7 3336.27,689.7 3382.27,689.7 3175.27,735.7 3221.27,735.7 3267.27,735.7 3313.27,735.7 3359.27,735.7
NetD1_2: D1.2 R23.2 | length 73.8
  Top Layer w25: R23.2@2973.39,1101.26 D1.2@2973.39,1175.04
NetD2_2: D2.2 R24.2 | length 71.8
  Top Layer w10: R24.2@3383.78,1808.2 D2.2@3383.78,1880
NetD3_2: D3.2 R25.2 | length 67.7
  Top Layer w10: D3.2@2662.52,656.45 2662.52,723.91 R25.2@2662.72,724.11
NetD5_1: D5.1 R30.1 | length 57.4
  Top Layer w10: D5.1@1219.07,1295.17 R30.1@1219.07,1352.5
NetD6_1: D6.1 R31.1 | length 66.2
  Top Layer w10: D6.1@1219.07,1148.06 R31.1@1219.07,1214.26
NetD7_2: D7.2 Q1.2
NetJ2_1: J2.1 L3.2
NetJ9_2: J9.2 R34.2 | length 93
  Top Layer w10: R34.2@3638.5,2232.5 3639.65,2233.65 J9.2@3639.65,2325
NetJ10_2: J10.2 R35.2 | length 93
  Top Layer w10: J10.2@3328.33,2325 3328.33,2233.68 R35.2@3329.51,2232.5
NetJ11_2: J11.2 R36.2 | length 92.9
  Top Layer w10: J11.2@3025,2325 3025,2233.5 R36.2@3026,2232.5
NetQ1_1: Q1.1 R33.2
NetQ1_3: Q1.3 Q2.3 R32.2
NetR1_1: R1.1 S1.3 | length 193.7
  Top Layer w10: R1.1@808.5,2422.5 810,2424 S1.3@810,2615.63
NetR2_1: R2.1 S2.3 | length 193.1
  Top Layer w10: R2.1@1235,2422.55 S2.3@1235,2615.63
NetR3_1: R3.1 S3.3 | length 193.1
  Top Layer w10: S3.3@1660,2615.63 1660,2422.81 R3.1@1660.16,2422.64
NetR4_2: R4.2 R5.2 | length 139.9
  Top Layer w10: R5.2@115,2200 R4.2@254.94,2200
NetR6_2: R6.2 S1.1 | length 193.2
  Top Layer w10: R6.2@609.9,2422.48 610,2422.58 S1.1@610,2615.63
NetR7_2: R7.2 S2.1 | length 193.1
  Top Layer w10: R7.2@1034.96,2422.52 1035,2422.57 S2.1@1035,2615.63
NetR8_2: R8.2 S3.1 | length 193.1
  Top Layer w10: R8.2@1459.83,2422.64 1460,2422.81 S3.1@1460,2615.63
NetR11_1: R11.1 R18.3 | length 101
  Top Layer w10: R18.3@115,1837.5 R11.1@115,1938.5
NetR18_1: R18.1 R19.2 | length 94.4
  Top Layer w10: R18.1@115,1637.5 115,1543.87 R19.2@115.52,1543.35
nFAULT: J6.13 R24.1 U1.16 | length 1984.3
  Top Layer w10: U1.16@3292.5,1704.06 3307.91,1704.06 3356.94,1753.08 R24.1@3383.78,1753.08
  Bottom Layer w10: J6.13@1912.5,2002.5 1967.81,2002.5 2080.24,1890.07 2080.24,1690.3 2190.57,1579.97 2373.38,1579.97 2642.14,1848.72 3150.78,1848.72 3270.76,1728.75 v3(3332.16,1728.75)
nSCS/DIR: R16.2 R17.2 U1.29 | length 829.5
  Top Layer w10: R17.2@2327.19,1602.81 2365,1602.81 2399.5,1637.31 R16.2@2399.5,1700.64 2991.94,1700.64 3027.89,1664.69 U1.29@3064.15,1664.69
nSLEEP: J6.15 U1.17 | length 1651.4
  Top Layer w10: U1.17@3266.91,1729.65 3291.2,1729.65 v3(3326.74,1765.18)
  Bottom Layer w10: J6.15@1912.5,2102.5 1963.28,2102.5 2106.64,1959.14 2106.71,1959.21 3171.78,1959.21 3326.74,1804.24 v3(3326.74,1765.18)
OUTA: J8.1 TP6.1 U1.11
OUTB: J8.2 TP9.1 U1.12
OUTC: J8.3 TP10.1 U1.13
PGND: C3.1 C4.2 C14.2 C15.2 C16.2 C17.2 C18.2 C19.2 C20.2 C21.2 C22.2 J7.2 NT2.2 R25.1 R33.1 R37.2 TP17.1 TP19.1 TP19.2 TP20.1 TP20.2 TP26.1 U1.10 U1.14
  other v1: 1904.27,81.7 2029.27,81.7 2154.27,81.7 2279.27,81.7 2404.27,81.7 2529.27,81.7 2654.27,81.7 2779.27,81.7 2904.27,81.7 3029.27,81.7 3154.27,81.7 3279.27,81.7 3404.27,81.7 3529.27,81.7 3654.27,81.7 3779.27,81.7 3904.27,81.7 4154.27,81.7 1966.77,206.7 2091.77,206.7 3841.77,206.7 1904.27,331.7 3529.27,331.7 3779.27,331.7 1966.77,456.7 2091.77,456.7 3466.77,456.7 3841.77,456.7 3966.77,456.7 1904.27,581.7 2029.27,581.7 3904.27,581.7 4029.27,581.7 1966.77,706.7 2091.77,706.7 2216.77,706.7 2341.77,706.7 2466.77,706.7 2591.77,706.7 3841.77,706.7 4091.77,706.7 1904.27,831.7 2029.27,831.7 2279.27,831.7 2404.27,831.7 2529.27,831.7 2654.27,831.7 2779.27,831.7 3529.27,831.7 3654.27,831.7 3904.27,831.7 4029.27,831.7 3466.77,956.7 3591.77,956.7 3716.77,956.7 3841.77,956.7 3966.77,956.7 4091.77,956.7 3529.27,1081.7 3654.27,1081.7 3779.27,1081.7 3904.27,1081.7 4029.27,1081.7 4154.27,1081.7 3466.77,1206.7 3591.77,1206.7 3716.77,1206.7 3841.77,1206.7 3966.77,1206.7 4091.77,1206.7 3529.27,1331.7 4154.27,1331.7 4154.27,1581.7 3529.27,1831.7 4154.27,1831.7 3591.77,1956.7 3716.77,1956.7 3841.77,1956.7 4091.77,1956.7 3779.27,2081.7 3904.27,2081.7 4029.27,2081.7 4154.27,2081.7 3841.77,2206.7 3966.77,2206.7 4091.77,2206.7 3904.27,2331.7 4154.27,2331.7 3966.77,2456.7 4091.77,2456.7 3841.77,2706.7
PWM: J6.3 U1.32 | length 1194.4
  Top Layer w10: J6.3@1912.5,1502.5 2402.22,1502.5 2505.35,1605.63 U1.32@3064.15,1605.63
PWM_EXT: J1.1 TP2.1 | length 230.3
  Top Layer w10: TP2.1@1642.5,672.2 J1.1@1642.5,902.5
PWM_SEL: J1.2 J6.4 | length 711.8
  Top Layer w10: J1.2@1542.5,902.5 1542.5,1232.5 J6.4@1812.5,1502.5
SCLK/ADVANCE: R13.2 R20.1 R26.2 U1.28 | length 1039.1
  Top Layer w10: R13.2@2399.5,1780.64 v2(2443.52,1780.64) 2505.35,1718.81 2505.35,1718.52 2999.34,1718.52 3033.49,1684.37 U1.28@3064.15,1684.37 ; R26.2@2657.5,1852.5 v3(2657.5,1890.07) R20.1@2657.5,1927.64
  Bottom Layer w10: v2(2443.52,1780.64) 2548.07,1780.64 v3(2657.5,1890.07)
SDI/SLEW: R14.2 R21.1 R27.2 U1.27 | length 1131.4
  Top Layer w10: R14.2@2399.5,1858.14 v2(2443.52,1858.14) 2565.27,1736.39 3006.74,1736.39 3039.08,1704.06 U1.27@3064.15,1704.06 ; R27.2@2742.5,1855.3 v3(2742.5,1891.47) R21.1@2742.5,1927.64
  Bottom Layer w10: v2(2443.52,1858.14) 2529.2,1858.14 2584,1912.94 2721.03,1912.94 v3(2742.5,1891.47)
SDO/MODE: R15.2 R22.1 R28.2 U1.26 | length 1245.8
  Top Layer w10: R15.2@2399.5,1936.33 v2(2443.52,1936.33) 2625.58,1754.27 3014.15,1754.27 3038.77,1729.65 U1.26@3089.74,1729.65 ; R28.2@2822.5,1855.3 v3(2822.5,1891.47) R22.1@2822.5,1927.64
  Bottom Layer w10: v2(2443.52,1936.33) 2777.64,1936.33 v3(2822.5,1891.47)
SIMO: J6.9 R14.1 | length 454.9
  Top Layer w10: J6.9@1912.5,1802.5 2022.5,1802.5 2078.14,1858.14 R14.1@2344.39,1858.14
SOMI: J6.11 R12.1 R15.1 | length 445.9
  Top Layer w10: J6.11@1912.5,1902.5 1946.36,1936.36 R12.1@2240.61,1936.36 R15.1@2344.39,1936.33
STE: J6.5 R16.1 | length 472.8
  Top Layer w10: J6.5@1912.5,1602.5 1912.76,1602.24 2022.5,1602.24 2120.9,1700.64 R16.1@2344.39,1700.64
SW_BUCK: L1.1 L2.1 R10.1 TP7.1 U1.4 | length 55.6
  Top Layer w10: 3131.87,1531.45 3148.8,1548.38 U1.4@3148.8,1580.04
VBAT: D7.1 J7.3 Q2.4 Q2.8 TP15.1
VBK: C6.1 D1.1 J13.3 L1.2 L2.2 NT1.2 R10.2 TP8.1
VCP: C1.1 R32.1 U1.7 | length 1223.2
  Top Layer w10: v3(3115.18,902.5) 3115.18,685 3158.7,641.48 R32.1@3296.83,641.48 ; U1.7@3207.85,1580.04 3207.93,1579.96 3207.93,1565.22 v3(3266.91,1506.24) C1.1@3266.91,1465.04
  Bottom Layer w10: v3(3115.18,902.5) 3266.91,1054.23 v3(3266.91,1506.24)
VM: C1.2 C3.2 C4.1 C14.1 C19.1 C20.1 C21.1 C22.1 D3.1 J7.1 L4.2 TP16.1 U1.8 U1.9
  other v1: 2279.27,206.7 2404.27,206.7 2529.27,206.7 2654.27,206.7 2779.27,206.7 2904.27,206.7 3029.27,206.7 3154.27,206.7 2341.77,331.7 2466.77,331.7 2279.27,456.7 2404.27,456.7 2529.27,456.7 2654.27,456.7 2779.27,456.7 2341.77,581.7 2591.77,581.7 2716.77,581.7
  other v3: 3328.33,1390 3360,1390 3328.33,1420.58 3360,1420.58
pads on no net: FID1.1 FID2.1 FID3.1 H1.1 H2.1 H3.1 H4.1 H5.0 H6.0 H7.0 H8.0 LBL1.0 SH-J1.0 SH-J2.0 SH-J3.0 SH-J4.0 SH-J5.0 SH-J6.0 SH-J7.0 SH-J8.0 SH-J9.0 SH-J10.0 SH-J11.0 SH-J12.0 SH-J13.0 SH-J14.0 SH-J15.0 SH-J16.0 U2.2 U2.3 U2.6 U2.8 U2.9 U2.10 U2.11 U2.12 U2.13 U2.14 U2.19 U2.22 U2.23 U2.24 U2.27 U2.28 U3.1 U4.1 U4.3 U4.10 U4.11 U4.16 U4.17 U4.18 U4.19 U4.20 U4.21 U4.22 U4.25 U4.26 U4.31 U4.32 U4.33 U4.34 U4.35 U4.36 U4.37 U4.38 U4.39 U4.40 U4.41 U4.42 U4.43 U4.46 U4.47 U4.48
